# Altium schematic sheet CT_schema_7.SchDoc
size 278 x 170 mm
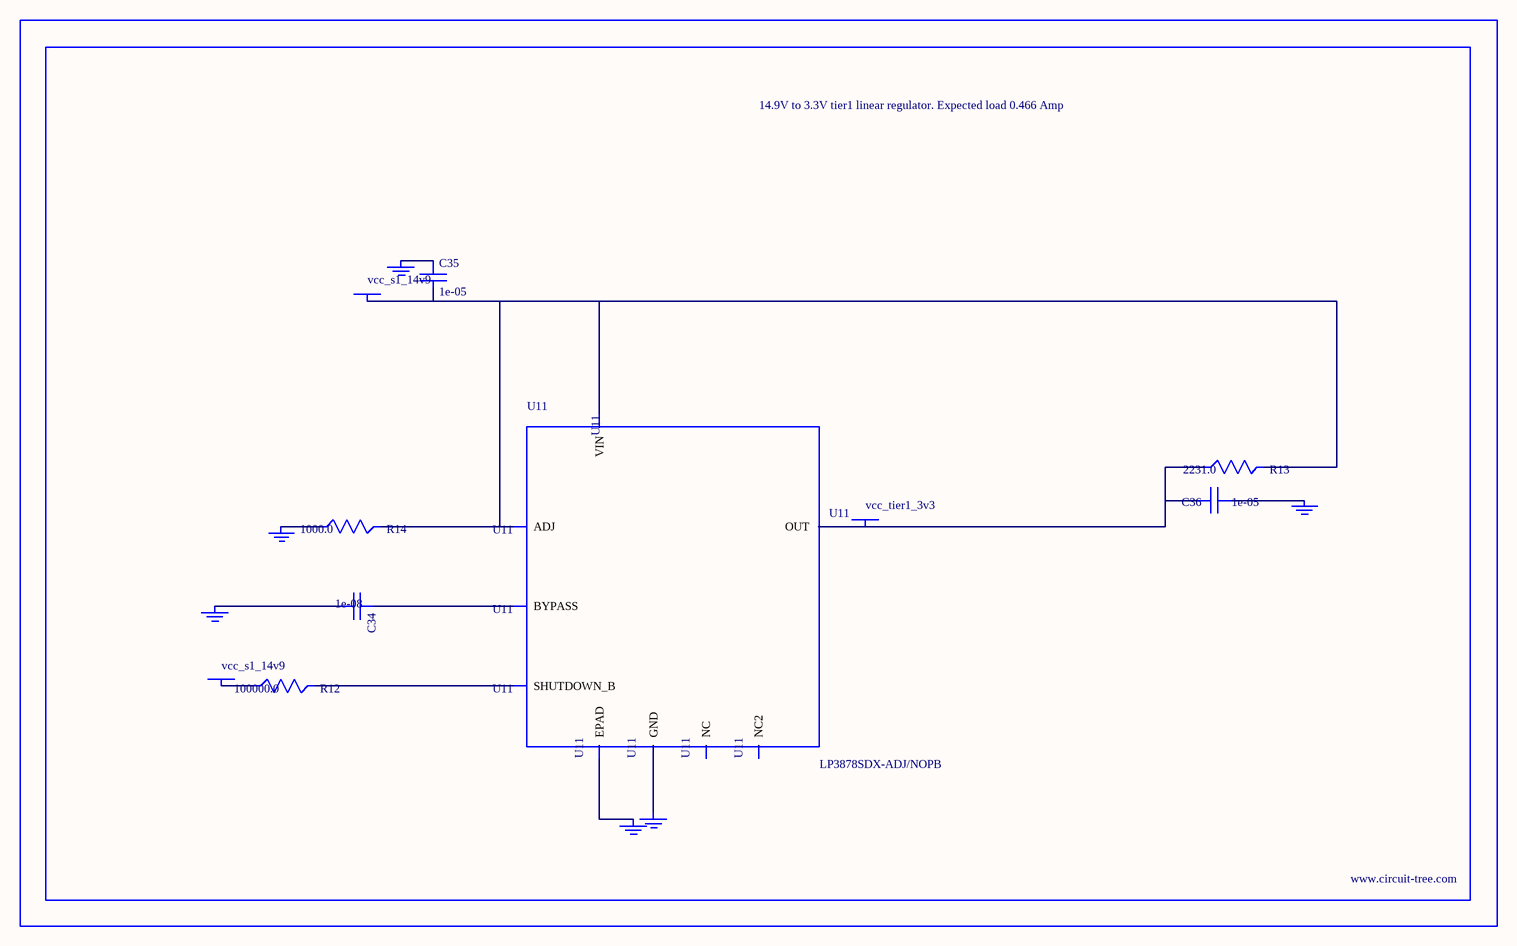
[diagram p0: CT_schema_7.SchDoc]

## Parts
BORDER6  (no value)
C34  1e-08  [C0402]
C35  1e-05  [C1210]
C36  1e-05  [C1210]
GND_INSTANCE_6_0  (no value)
GND_INSTANCE_6_1  (no value)
GND_INSTANCE_6_2  (no value)
GND_INSTANCE_6_3  (no value)
GND_INSTANCE_6_4  (no value)
GND_INSTANCE_6_5  (no value)
POWER_INSTANCE_6_0  vcc_s1_14v9
POWER_INSTANCE_6_1  vcc_s1_14v9
POWER_INSTANCE_6_2  vcc_tier1_3v3
R12  100000.0  [R0603]
R13  2231.0  [R0603]
R14  1000.0  [R0603]
U11  LP3878SDX-ADJ/NOPB  [WSON-8]

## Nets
NetC34_1: C34.1 U11.1(BYPASS)
NetC34_2: C34.2 GND_INSTANCE_6_0.0(GND)
NetC35_1: C35.1 GND_INSTANCE_6_1.0(GND)
NetC35_2: C35.2 POWER_INSTANCE_6_0.0(PWR) R13.2 R14.2 U11.4(VIN) U11.6(ADJ)
NetC36_1: C36.1 GND_INSTANCE_6_2.0(GND)
NetC36_2: C36.2 POWER_INSTANCE_6_2.0(PWR) R13.1 U11.5(OUT)
NetGND_INSTANCE_6_3_0: GND_INSTANCE_6_3.0(GND) R14.1
NetGND_INSTANCE_6_4_0: GND_INSTANCE_6_4.0(GND) U11.PAD(EPAD)
NetGND_INSTANCE_6_5_0: GND_INSTANCE_6_5.0(GND) U11.3(GND)
NetPOWER_INSTANCE_6_1_0: POWER_INSTANCE_6_1.0(PWR) R12.1
NetR12_2: R12.2 U11.8(SHUTDOWN_B)

Not connected (* = marked no-connect by the designer): U11 2(NC) 7(NC2)

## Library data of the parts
BORDER6 = BORDER_PAGE6
C34 = C0402C103K3RAC
C35 = C1210C106K5PACTU
C36 = GRM32DR61E106MA12L
GND_INSTANCE_6_0-GND_INSTANCE_6_5 = GND
POWER_INSTANCE_6_0-POWER_INSTANCE_6_2 = PWR
R12 = RC0603JR-07100KL
R13 = R13
R14 = RC0603JR-071KL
